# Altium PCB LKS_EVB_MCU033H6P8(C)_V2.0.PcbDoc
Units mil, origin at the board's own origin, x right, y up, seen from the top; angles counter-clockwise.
Board outline 2625 x 1560 mil, 2 copper layers (Top Layer, Bottom Layer); 24 components, 26 nets, 123 pads, 27 vias.
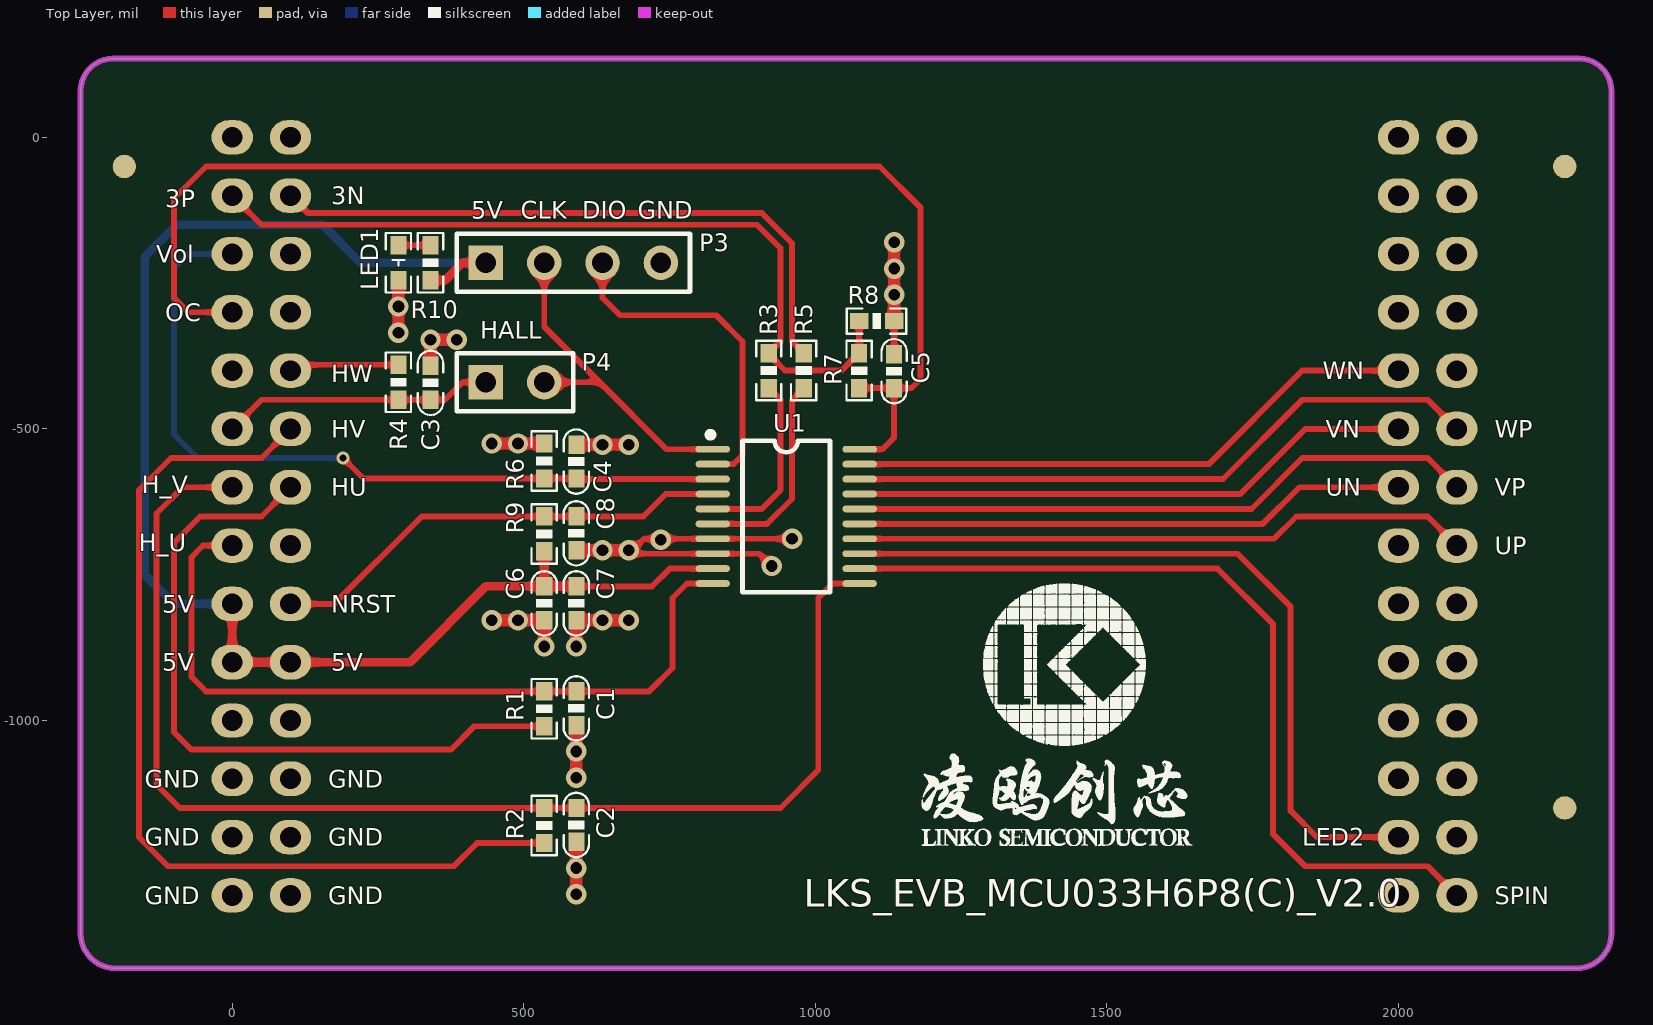
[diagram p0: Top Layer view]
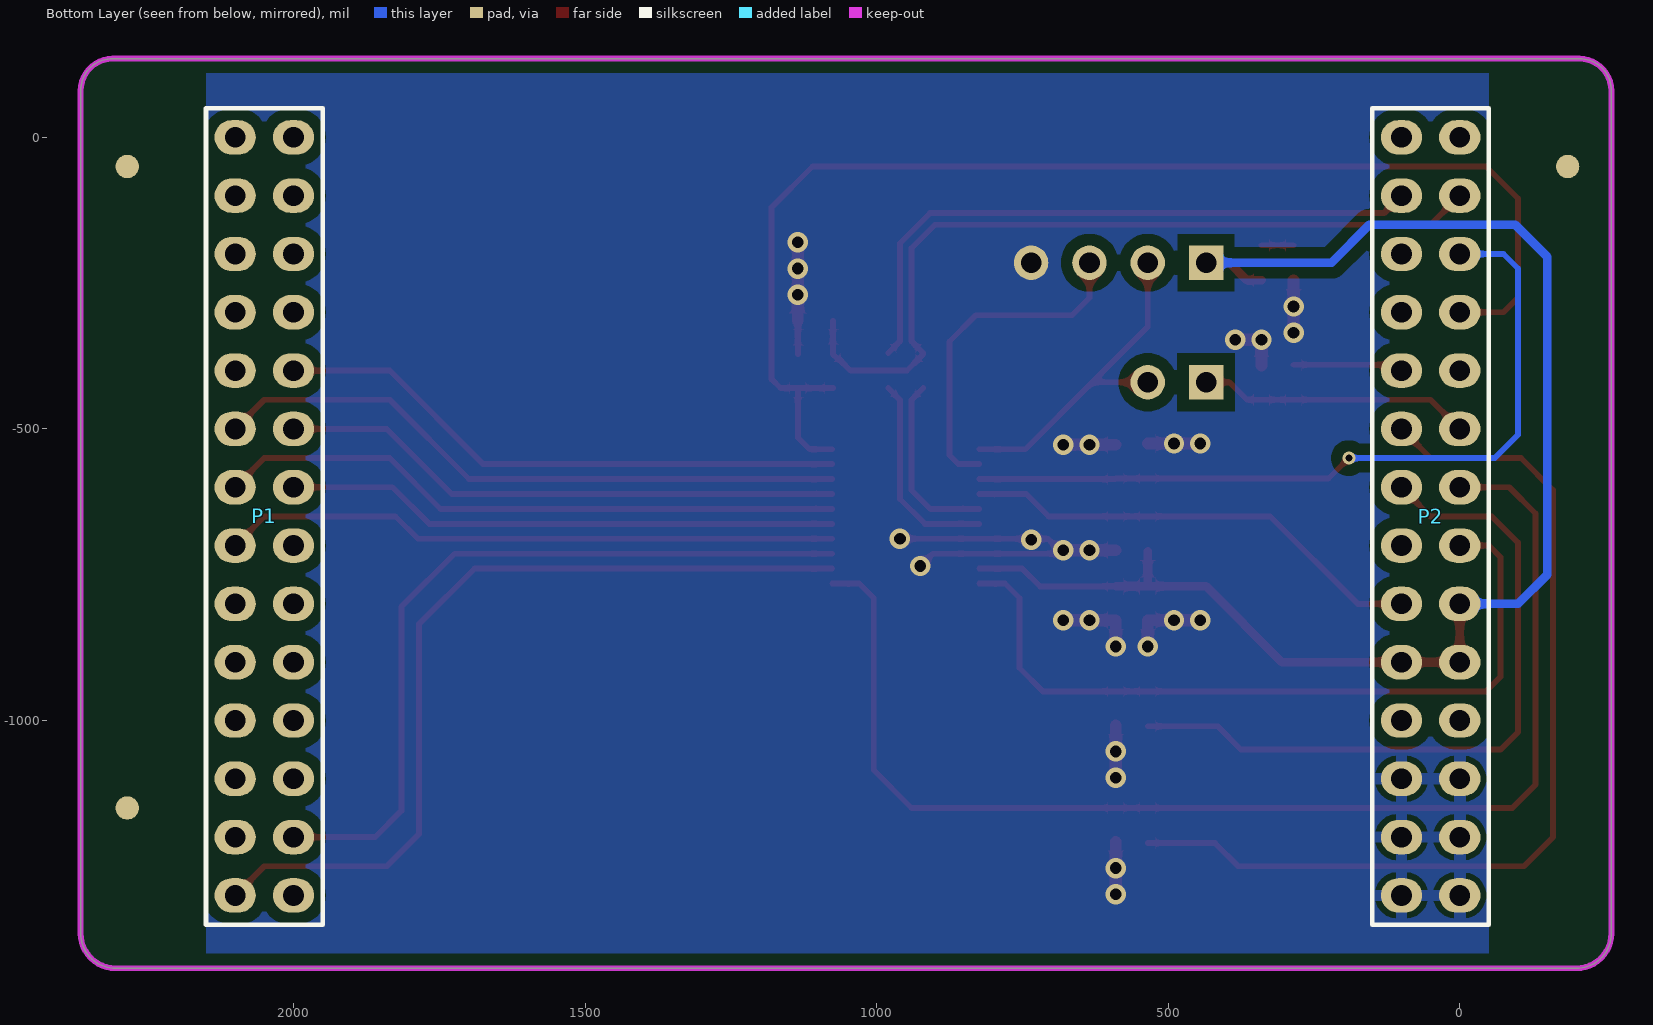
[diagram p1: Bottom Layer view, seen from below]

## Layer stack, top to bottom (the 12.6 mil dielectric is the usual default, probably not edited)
Top Solder: solder mask 0.4, Solder Resist, Dk 3.5
Top Layer: signal copper 1.4
Dielectric 1: dielectric 12.6, FR-4, Dk 4.8
Bottom Layer: signal copper 1.4
Bottom Solder: solder mask 0.4, Solder Resist, Dk 3.5

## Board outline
-260,-1365 ccw(c-200,-1365) -200,-1425 2305,-1425 ccw(c2305,-1365) 2365,-1365 2365,80 ccw(c2310,80) 2310,135 -205,135 ccw(c-205,80) -260,80

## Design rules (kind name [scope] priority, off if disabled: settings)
Clearance Clearance_2 [InPolygon] p1: gap=20 ignorepadtopadclearanceinfootprint=FALSE
Clearance Clearance_1 [InNet('+5V')] p2: gap=10 ignorepadtopadclearanceinfootprint=FALSE
Clearance [All] p3: gap=8 ignorepadtopadclearanceinfootprint=FALSE
ComponentClearance [All] p1: gap=0 collisioncheckmode=3 verticalgap=0 showdistances=FALSE
MinimumSolderMaskSliver [All] p1: minsoldermaskwidth=0
PolygonConnect PolygonConnect_1 [HasFootprint('HDR 2X14 顶层')] p1: connectstyle=Relief reliefconductorwidth=20 reliefentries=4 polygonreliefangle="90 Angle" airgapwidth=10
PolygonConnect [All] p2: connectstyle=Direct reliefconductorwidth=10 reliefentries=4 polygonreliefangle="90 Angle" airgapwidth=10
RoutingVias [All] p1: holewidth=28 width=50 viastyle="Through Hole" minholewidth=28 minwidth=50 maxholewidth=28 maxwidth=50
SilkToSilkClearance [All] p1: silktosilkclearance=5
SilkToSolderMaskClearance [IsPad] p1: minsilkscreentomaskgap=5 clearancetoexposedcopper=TRUE
SolderMaskExpansion [All] p1: expansion=4 istentingtop=FALSE
Width [All] p1: maxlimit=100 minlimit=1 preferedwidth=10
26 further rules are at their usual default settings.

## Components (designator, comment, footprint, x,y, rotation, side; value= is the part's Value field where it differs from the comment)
C1 "10nF/50V" 0603C 590,-979 r270 top
C2 "10nF/50V" 0603C 590,-1179 r270 top
C3 "10nF/50V" 0603C 340,-421 r90 top
C4 "100nF/50V" 0603C 590,-555.95 r270 top
C5 "1nF/50V" 0603C 1135,-400.95 r270 top
C6 "10uF/16V" 0603C 535,-799.05 r90 top
C7 "100nF/50V" 0603C 590,-799.05 r90 top
C8 "100nF/50V" 0603C 590,-679 r270 top
LED1 "LED" "LED 0603R" 285,-215 r270 top
P1 "Header 14X2A" "HDR 2X14 顶层" 2050,-650 r180 bottom locked
P2 "Header 14X2A" "HDR 2X14 顶层" 50,-650 r180 bottom locked
P3 "Header 4" "HDR 1X4" 435,-215 r0 top locked
P4 "Header 2" "HDR 1X2" 435,-420 r0 top
R1 "2K" 0603R 535,-980 r90 top value=K
R2 "2K" 0603R 535,-1180 r90 top value=K
R3 "1K1%" 0603R 920,-400 r270 top value=K
R4 "2K" 0603R 285,-420 r270 top value=K
R5 "1K1%" 0603R 980,-400 r270 top value=K
R6 "1K1%" 0603R 535,-555 r270 top value=K
R7 "1K1%" 0603R 1075,-400 r90 top value=K
R8 "10R" 0603R 1105,-315 r0 top value=K
R9 "20K1%" 0603R 535,-680 r90 top value=K
R10 "3.3K" 0603R 340,-215 r90 top value=330
U1 "LKS32MC033H6P8C" TSSOP-20 950,-650 r0 top locked

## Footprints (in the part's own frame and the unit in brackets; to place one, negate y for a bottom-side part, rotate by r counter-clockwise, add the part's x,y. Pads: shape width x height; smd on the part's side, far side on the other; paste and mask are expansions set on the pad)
0603C [mm] "电容"
  rect 0.8x0.7 smd: 1(-0.737,0) 2(0.738,0)
  silkscreen extent -1.4,-0.55 1.4,0.55, body extent -0.8,-0.41 0.8,0.41, height 0.81
0603R [mm] "电阻"
  rect 0.8x0.7 smd: 1(-0.762,0) 2(0.762,0)
  silkscreen extent -1.3,-0.55 1.3,0.55, body extent -0.8,-0.4 0.8,0.4, height 0.45
"HDR 1X2" [mm] "单排针 2.54mm"
  rect 1.5x1.5 hole 0.9: 1(0,0)
  round 1.5 hole 0.9: 2(2.54,0)
  silkscreen extent -1.27,-1.27 3.81,1.27, body extent -1.27,-1.27 3.81,1.27, height 8.5
"HDR 1X4" [mm] "单排针 2.54mm"
  rect 1.5x1.5 hole 0.9: 1(0,0)
  round 1.5 hole 0.9: 2(2.54,0) 3(5.08,0) 4(7.62,0)
  silkscreen extent -1.27,-1.27 8.89,1.27, body extent -1.27,-1.27 8.89,1.27, height 8.5
"HDR 2X14 顶层" [mm] "双排针 2.54mm 顶层"
  oval 1.8x1.5 hole 0.9: 1(1.27,16.51) 2(1.27,13.97) 3(1.27,11.43) 4(1.27,8.89) 5(1.27,6.35) 6(1.27,3.81) 7(1.27,1.27) 8(1.27,-1.27) 9(1.27,-3.81) 10(1.27,-6.35) 11(1.27,-8.89) 12(1.27,-11.43) 13(1.27,-13.97) 14(1.27,-16.51) 15(-1.27,16.51) 16(-1.27,13.97) 17(-1.27,11.43) 18(-1.27,8.89) 19(-1.27,6.35) 20(-1.27,3.81) 21(-1.27,1.27) 22(-1.27,-1.27) 23(-1.27,-3.81) 24(-1.27,-6.35) 25(-1.27,-8.89) 26(-1.27,-11.43) 27(-1.27,-13.97) 28(-1.27,-16.51)
  silkscreen extent -2.54,-17.78 2.54,17.78, body extent -2.54,-17.78 2.54,17.78, height 8.5
"LED 0603R" [mm] "LED"
  rect 0.8x0.7 smd: 1(-0.762,0) 2(0.762,0)
  silkscreen extent -1.3,-0.55 1.3,0.55, body extent -0.8,-0.4 0.8,0.4, height 0.47
TSSOP-20 [mm]
  oval 1.5x0.3 smd: 1(-3.2,2.925) 2(-3.2,2.275) 3(-3.2,1.625) 4(-3.2,0.975) 5(-3.2,0.325) 6(-3.2,-0.325) 7(-3.2,-0.975) 8(-3.2,-1.625) 9(-3.2,-2.275) 10(-3.2,-2.925) 11(3.2,-2.925) 12(3.2,-2.275) 13(3.2,-1.625) 14(3.2,-0.975) 15(3.2,-0.325) 16(3.2,0.325) 17(3.2,0.975) 18(3.2,1.625) 19(3.2,2.275) 20(3.2,2.925)
  silkscreen extent -3.43,-3.3 1.91,3.69, body extent -3.2,-3.25 3.2,3.25, height 1.03

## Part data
C1 C2 C3: library part CAP, "Capacitor"
C4 C5 C6 C7 C8: library part C, "Capacitor"
LED1: "LED_Light"
P1 P2: "Header, 14-Pin, Dual row"
P3: "Header, 4-Pin"
P4: "Header, 2-Pin"
R1 R2 R3 R4 R5 R6 R7 R8 R9 R10: library part Res, "Resistor"
U1: "芯片"

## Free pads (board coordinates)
  round 40 all layers, no hole: 1(-185,-50) 2(2285,-50) 3(2285,-1150)

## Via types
v1: diameter 35, hole 20, Top Layer to Bottom Layer, 26 vias
v2: diameter 22, hole 12, Top Layer to Bottom Layer, 1 vias

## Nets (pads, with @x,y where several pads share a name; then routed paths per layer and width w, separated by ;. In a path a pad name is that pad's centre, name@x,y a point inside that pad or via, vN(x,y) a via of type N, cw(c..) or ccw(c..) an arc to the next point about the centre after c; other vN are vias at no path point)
+5V: C6.2 C7.2 P2.9 P2.10 P2.24 P3.1 R9.1 R10.1 U1.9 | length 2508.3
  Top Layer w10: C7.2 720,-770 750.43,-739.57 U1.9
  Top Layer w15: P2.9 P2.10 P2.24 305,-900 435,-770 C6.2 ; R10.1 365,-245 395,-215 P3.1 ; R9.1 C6.2 ; C7.2 C6.2
  Bottom Layer w15: P2.9 -100,-800 -150,-750 -150,-205 -95,-150 155,-150 220,-215 P3.1
GND: C1.2 C2.2 C3.2 C4.1 C5.1 C6.1 C7.1 C8.2 LED1.2 P2.12 P2.13 P2.14 P2.26 P2.27 P2.28 P3.4 R6.1 R8.2 U1.7 U1.8 | length 1621.1
  Top Layer w10: v1(680,-708.05) 686.62,-708.05 706.29,-688.39 U1.7 v1(960,-688.39) ; v1@692.69,-713.98 U1.8 903.98,-713.98 v1(925,-735) ; C5.1 R8.2
  Top Layer w20: v1(285,-335) v1(285,-290) LED1.2 ; C3.2 v1(340,-346.95) v1(385,-346.95) ; v1(445,-828.05) v1(490,-828.05) C6.1 v1(535,-873.05) ; v1(445,-525) v1(490,-525) R6.1 ; v1(590,-1298.05) v1(590,-1253.05) C2.2 ; v1(590,-1098.05) v1(590,-1053.05) C1.2 ; v1(590,-873.05) C7.1 v1(635,-828.05) v1(680,-828.05) ; C8.2 v1(635,-708.05) v1(680,-708.05) ; C4.1 v1(635,-526.95) v1(680,-526.95) ; R8.2 v1(1135,-270) v1(1135,-225) v1(1135,-180)
  other v1: 735,-690
GND0: P2.16 R5.1 | length 1090.4
  Top Layer w10: P2.16 130,-130 908.28,-130 960,-181.72 960,-350 R5.1
HALL_U: C1.1 P2.8 R1.2 U1.10 | length 1334.5
  Top Layer w10: P2.8 -50,-700 -70,-720 -70,-925 -45,-950 635,-950 715,-950 755,-910 755,-790 779.84,-765.16 U1.10
HALL_V: C2.1 P2.7 R2.2 U1.11 | length 2168.4
  Top Layer w10: P2.7 -85,-600 -130,-645 -130,-1110 -90,-1150 R2.2 C2.1 940,-1150 1005,-1085 1005,-790 1029.84,-765.16 U1.11
HALL_W: C3.1 P2.6 P4.1 R4.2 | length 468.1
  Top Layer w10: P2.6 50,-450 R4.2 C3.1 365,-450 395,-420 P4.1
HU: P2.21 R1.1 | length 1228.3
  Top Layer w10: P2.21 50,-650 -55,-650 -100,-695 -100,-1020 -70,-1050 375,-1050 415,-1010 R1.1
HV: P2.20 R2.1 | length 1630.8
  Top Layer w10: P2.20 50,-550 -105,-550 -160,-605 -160,-1200 -110,-1250 380,-1250 420,-1210 R2.1
HW: P2.19 R4.1 | length 189.1
  Top Layer w10: P2.19 110,-390 R4.1
LED2: P1.13 U1.13 | length 1330.4
  Top Layer w10: U1.13 1723.98,-713.98 1815,-805 1815,-1155 1860,-1200 P1.13
NetLED1_1: LED1.1 R10.2 | length 55
  Top Layer w10: LED1.1 R10.2
NRST: C8.1 P2.23 R9.2 U1.4 | length 802
  Top Layer w10: P2.23 175,-800 325,-650 R9.2 C8.1 705,-650 743.39,-611.61 U1.4
OC: C5.2 P2.4 R7.1 U1.20 | length 2170.6
  Top Layer w10: P2.4 -75,-300 -100,-275 -100,-105 -45,-50 1110,-50 1180,-120 1180,-415 1165,-430 C5.2 ; R7.1 C5.2 ; U1.20 1115.16,-534.84 1135,-515 C5.2
OPA1_IN: R5.2 U1.6 | length 352
  Top Layer w10: U1.6 917.2,-662.8 960,-620 960,-450 R5.2
OPA1_IP: R3.2 U1.5 | length 312.6
  Top Layer w10: U1.5 907.8,-637.2 940,-605 940,-450 R3.2
PGND: P2.2 R3.1 R7.2 R8.1 | length 1402.7
  Top Layer w10: P2.2 50,-150 900,-150 940,-190 940,-350 R3.1 920,-371.97 948.03,-400 1045,-400 1064.25,-380.75 1066.22,-380.75 1075,-371.97 R7.2 R8.1
SPin: P1.28 U1.12 | length 1467
  Top Layer w10: U1.12 1689.57,-739.57 1785,-835 1785,-1195 1840,-1250 2050,-1250 P1.28
SWCLK: P3.2 P4.2 U1.1 | length 580.9
  Top Layer w10: P4.2 630,-420 ; P3.2 535,-325 630,-420 ; U1.1 744.84,-534.84 630,-420
SWDIO: P3.3 U1.2 | length 583.4
  Top Layer w10: P3.3 635,-275 665,-305 830,-305 875,-350 875,-545 859.91,-560.09 824.36,-560.09 U1.2
UN: P1.7 U1.15 | length 950
  Top Layer w10: U1.15 1767.2,-662.8 1830,-600 P1.7
UP: P1.22 U1.14 | length 1060.6
  Top Layer w10: U1.14 1786.61,-688.39 1825,-650 2050,-650 P1.22
VN: P1.6 U1.17 | length 970.2
  Top Layer w10: U1.17 1728.39,-611.61 1840,-500 P1.6
Vol_ADC: C4.2 P2.3 R6.2 U1.3 | length 1350.9
  Top Layer w10: v2(190,-550) 225,-585 R6.2 C4.2 591.02,-586.02 U1.3
  Bottom Layer w10: P2.3 -75,-200 -100,-225 -100,-510 -60,-550 v2(190,-550)
VP: P1.21 U1.16 | length 1080.8
  Top Layer w10: U1.16 1747.8,-637.2 1835,-550 2050,-550 P1.21
WN: P1.5 U1.19 | length 990.5
  Top Layer w10: U1.19 1674.57,-560.43 1835,-400 P1.5
WP: P1.20 U1.18 | length 1101.1
  Top Layer w10: U1.18 1698.98,-586.02 1835,-450 2050,-450 P1.20
pads on no net: P1.1 P1.2 P1.3 P1.4 P1.8 P1.9 P1.10 P1.11 P1.12 P1.14 P1.15 P1.16 P1.17 P1.18 P1.19 P1.23 P1.24 P1.25 P1.26 P1.27 P2.1 P2.5 P2.11 P2.15 P2.17 P2.18 P2.22 P2.25

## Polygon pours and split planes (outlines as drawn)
GND on Bottom Layer "10" (solid, remove dead copper, pour order 0): -50,135 -50,-1425 2150,-1425 2150,135

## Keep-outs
Keep-Out Layer:
  the board outline again, w10

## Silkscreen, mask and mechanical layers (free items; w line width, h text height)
Top Overlay:
  drawing of 144 lines, arcs and shapes, not listed
  text "3N" at 170,-115 h30
  text "3P" at -115,-120 h30
  text "5V" at 410,-140 h30
  text "CLK" at 495,-140 h30
  text "DIO" at 600,-140 h30
  text "GND" at 695,-140 h30
  text "Vol" at -130,-215 h30
  text "OC" at -115,-315 h30
  text "HALL" at 425,-345 h30
  text "WN" at 1870,-415 h30
  text "HW" at 170,-420 h30
  text "HV" at 170,-515 h30
  text "VN" at 1875,-515 h30
  text "WP" at 2165,-515 h30
  text "H_V" at -155,-610 h30
  text "HU" at 170,-615 h30
  text "UN" at 1875,-615 h30
  text "VP" at 2165,-615 h30
  text "H_U" at -160,-710 h30
  text "UP" at 2165,-715 h30
  text "5V" at -120,-815 h30
  text "NRST" at 170,-815 h30
  text "5V" at -120,-915 h30
  text "5V" at 170,-915 h30
  text "GND" at -150,-1115 h30
  text "GND" at 165,-1115 h30
  text "GND" at -150,-1215 h30
  text "GND" at 165,-1215 h30
  text "LED2" at 1835,-1215 h30
  text "GND" at -150,-1315 h30
  text "GND" at 165,-1315 h30
  text "SPIN" at 2165,-1315 h30
  text "LKS_EVB_MCU033H6P8(C)_V2.0" at 980,-1335 h80
Top Solder:
  circle w78: c2285,-1150 r17
  circle w78: c-185,-50 r17
  circle w78: c2285,-50 r17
